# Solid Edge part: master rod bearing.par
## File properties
Author: Robert a Rhodes jr
Template: Normal.par
Last saved by: Cadcim
Revision: 5
Application: Solid Edge
Accuracy: 0.99
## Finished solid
Body 1: solid body, 4 faces, 4 edges, 0 vertices.
  Faces by surface: cylinder 2, plane 2
  Edges by curve: circle 4
Bounding box of the edges (mm): 52.000 x 52.000 x 70.000, from (-26, -26, -70) to (26, 26, 0).
Cylindrical faces by radius (mm): R23 x1, R26 x1
Planar faces by outward normal: +z 1, -z 1
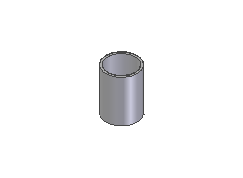
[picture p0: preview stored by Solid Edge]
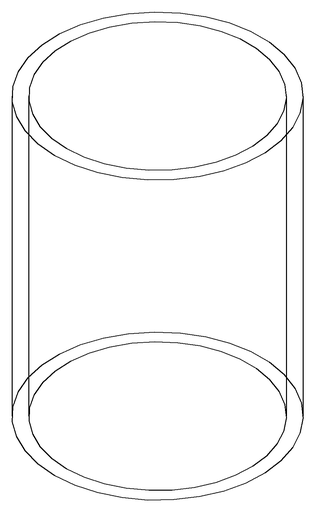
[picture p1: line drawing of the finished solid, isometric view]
